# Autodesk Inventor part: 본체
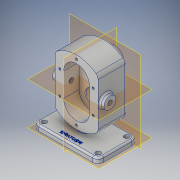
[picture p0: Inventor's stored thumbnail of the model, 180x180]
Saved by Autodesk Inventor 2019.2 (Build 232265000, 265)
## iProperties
Created: 2019-03
Part Number: 본체
Material: 알루미늄 6061
Document SubType Name: Modeling
Designer: User
Density: 2.7 g/cm^3
Appearance: 알루미늄 - 평지
Author: User
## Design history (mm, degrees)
sketch "스케치1"
  geometry: L1 (0, -14.6)-(0, 87.6) reference; L2 (84, 0)-(-84, 0) reference; L3 (60, 73)-(-60, 73); L4 (-60, 73)-(-60, 0); L5 (-60, 0)-(60, 0); L6 (60, 0)-(60, 73); L7 (60, 73)-(-60, 0); L8 (-60, 73)-(60, 0); 2 further points
  constraints: 12 end point, 3 midpoint, 2 parallel, 1 collinear, 1 horizontal, 1 perpendicular
  dimensions: "d0" = 120 distance of L5.end L4.end; "d1" = 73 distance of L4.end L3.end
extrude "돌출1" new body sketch "스케치1" distance "d2" = 10; taper "d3" = 0 deg
sketch "스케치2"
  geometry: L1 (-40, 138)-(40, 138); L2 (40, 122.721)-(40, 33.279); L3 (40, 18)-(-40, 18); L4 (-40, 33.279)-(-40, 122.721); L5 (-40, 138)-(40, 18); L6 (40, 138)-(-40, 18); L7 (0, -40.2)-(0, 241.2) reference; L8 (-111.6, 0)-(88.6, 0) reference; L9 (0, 241.2)-(0, -40.2) reference; L10 (-60, 0)-(60, 0) reference; A1 r 60 centre (0, 78) between (40, 122.721) and (-40, 122.721); A2 r 60 centre (0, 78) between (-40, 33.279) and (40, 33.279); 3 further points
  constraints: 12 end point, 4 point on circle, 3 midpoint, 3 parallel, 2 centre point, 2 coincident, 1 horizontal, 1 perpendicular, 1 point on line, 1 tangent
  dimensions: "d5" = 138 distance between parallel lines of L10 L1; "d6" = 78 distance from line of L8 point (0, 78); "d7" = 60 radius of A1; "d8" = 60 radius of A2; "d9" = 80 distance between parallel lines of L2 L4
extrude "돌출2" join sketch "스케치2" distance "d10" = 53; taper "d11" = 0 deg
sketch "스케치4"
  geometry: L1 (-6, -43)-(6, -43); L2 (6, -43)-(6, 0); L3 (6, 0)-(-6, 0); L4 (-6, 0)-(-6, -43); L5 (-6, -43)-(6, 0); L6 (6, -43)-(-6, 0); L7 (0, 14.6)-(0, -87.6) reference; L8 (-84, 0)-(84, 0) reference; 3 further points
  constraints: 12 end point, 3 midpoint, 2 parallel, 1 collinear, 1 horizontal, 1 perpendicular, 1 point on line
  dimensions: "d17" = 12 distance of L1.start L1.end; "d18" = 43 distance of L3.end L1.start
extrude "돌출4" join sketch "스케치4" distance "d19" = 78; taper "d20" = 0 deg
sketch "스케치3"
  geometry: L1 (0, -27.6)-(0, 165.6) reference; L2 (-84, 0)-(84, 0) reference; L3 (0, 100)-(0, 56); L4 (-24, 100)-(-24, 56); L5 (24, 56)-(24, 100); A1 r 24 centre (0, 100) between (24, 100) and (-24, 100); A2 r 24 centre (0, 56) between (-24, 56) and (24, 56); 2 further points
  constraints: 8 end point, 4 point on circle, 4 tangent, 2 centre point, 2 point on line, 1 midpoint, 1 parallel
  dimensions: "d12" = 24 radius of A1; "d13" = 44 distance of L5.start L5.end; "d14" = 78 distance from line of L2 point (0, 78)
extrude "돌출3" cut sketch "스케치3" distance "d15" = 29; taper "d16" = 0 deg
sketch "스케치5"
  geometry: L1 (60, -27.6)-(60, 165.6) reference; L2 (144, 0)-(-24, 0) reference; C1 r 19 at (60, 100); 1 further point
  constraints: 1 centre point, 1 point on line
  dimensions: "d22" = 38 diameter of C1; "d23" = 100 distance from line of L2 C1.centre
extrude "돌출5" join sketch "스케치5" distance "d24" = 17; taper "d25" = 0 deg
sketch "스케치6"
  geometry: A1 r 24 centre (0, 100) between (24, 100) and (-24, 100) reference; 2 further points
  constraints: 1 coincident
hole "구멍1" sketch "스케치6" at (0, 100) diameter "d26" = 17; stored, may be unused: countersink angle "d30" = 90 deg, drill point angle "d32" = 0 deg; dims "d27" = 6, "d28" = 25, "d29" = 15, "d31" = 10
sketch "스케치7"
  geometry: C1 r 19 at (0, 0) reference; 2 further points
  constraints: 1 coincident
hole "구멍2" sketch "스케치7" at (0, 0) diameter "d33" = 28; stored, may be unused: countersink angle "d37" = 90 deg, drill point angle "d39" = 0 deg; dims "d34" = 6, "d35" = 25, "d36" = 15, "d38" = 7.3
sketch "스케치8"
  geometry: A1 r 24 centre (0, 56) between (-24, 56) and (24, 56) reference; 2 further points
  constraints: 1 coincident
hole "구멍3" sketch "스케치8" at (0, 56) diameter "d40" = 25; stored, may be unused: countersink angle "d44" = 90 deg, drill point angle "d46" = 0 deg; dims "d41" = 6, "d42" = 25, "d43" = 15, "d45" = 15
sketch "스케치9"
  geometry: L1 (0, -35)-(0, 91) reference; L2 (-27.6, 0)-(165.6, 0) reference; L3 (56, 53)-(100, 53) reference; C1 r 11 at (78, 39); 1 further point
  constraints: 1 centre point
  dimensions: "d47" = 22 diameter of C1; "d48" = 78 distance from line of L1 C1.centre; "d49" = 14 distance from line of L3 C1.centre
extrude "돌출6" join sketch "스케치9" distance "d50" = 8; taper "d51" = 0 deg
sketch "스케치10"
  geometry: C1 r 11 at (0, 0) reference; 2 further points
  constraints: 1 coincident
hole "구멍4" sketch "스케치10" at (0, 0) diameter "d52" = 8.376; stored, may be unused: countersink angle "d56" = 90 deg, drill point angle "d58" = 0 deg; dims "d53" = 30, "d54" = 25, "d55" = 15, "d57" = 27.3
sketch "스케치11"
  geometry: L1 (0, -27.6)-(0, 165.6) reference; L2 (-51, 100)-(51, 100); A1 r 31 centre (0, 100) between (0, 131) and (31, 100); A2 r 24 centre (0, 100) between (24, 100) and (-24, 100) reference; 2 further points
  constraints: 3 point on circle, 3 point on line, 2 end point, 1 centre point, 1 concentric, 1 horizontal, 1 midpoint
  dimensions: "d59" = 62 diameter of A1
hole "구멍6" sketch "스케치11" at (0, 131), (31, 100), (-31, 100) diameter "d67" = 4.134; stored, may be unused: countersink angle "d71" = 90 deg, drill point angle "d73" = 118 deg; dims "d68" = 10, "d69" = 25, "d70" = 15, "d72" = 12
node "오프셋 78"
fillet "모깎기1" dims "d75" = 10
sketch "스케치12"
  geometry: A1 r 10 centre (-50, -63) between (-60, -63) and (-50, -73) reference; A2 r 10 centre (50, -63) between (50, -73) and (60, -63) reference; A3 r 10 centre (50, -10) between (60, -10) and (50, 0) reference; A4 r 10 centre (-50, -10) between (-50, 0) and (-60, -10) reference; 5 further points
  constraints: 4 coincident
hole "구멍7" sketch "스케치12" at (-50, -63), (50, -63), (50, -10), (-50, -10) diameter "d76" = 9; stored, may be unused: countersink angle "d80" = 90 deg, drill point angle "d82" = 118 deg; dims "d77" = 10, "d78" = 25, "d79" = 15, "d81" = 12
sketch "스케치13"
  geometry: L1 (114, -9.7)-(114, -17) reference; L2 (81, -17)-(119, -17) reference; L3 (114, -16.3)-(114.404, -17); L4 (114, -17)-(114.404, -17); L5 (114, -16.3)-(114, -17); L6 (100, 106)-(100, -45); L7 (0, 136.2)-(0, -75.2) reference; 1 further point
  constraints: 8 end point, 2 collinear, 2 point on line, 1 vertical
  dimensions: "d84" = 30 deg angle of L3 L5; "d85" = 0.7 distance from line of L2 L3.start; "d86" = 100 distance between parallel lines of L7 L6
revolve "회전1" sketch "스케치13" stored, may be unused: angle "d87" = 90 deg
chamfer "모따기1" distance "d88" = 1; stored, may be unused: second distance "d89" = 2, angle "d90" = 45 deg
fillet "모깎기2" dims "d91" = 0.5
fillet "모깎기4" dims "d93" = 10
fillet "모깎기3" dims "d92" = 3
fillet "모깎기5" dims "d94" = 3
fillet "모깎기6" dims "d95" = 3
fillet "모깎기7" dims "d96" = 3
sketch "스케치14"
  geometry: L1 (-50, -73)-(50, -73) reference; L2 (-60, -10)-(-60, -63) reference; 2 further points
  constraints: 1 other
  dimensions: "d97" = 10 distance from line of L1 point (0, -63); "d98" = 60 distance from line of L2 point (0, -63)
feature "엠보싱1" sketch "스케치14" dims "d99" = 0.5, "d100" = 0
node "솔리드1"
mirror "미러2"
mirror "미러3"
other parameters: "d74" = 78
